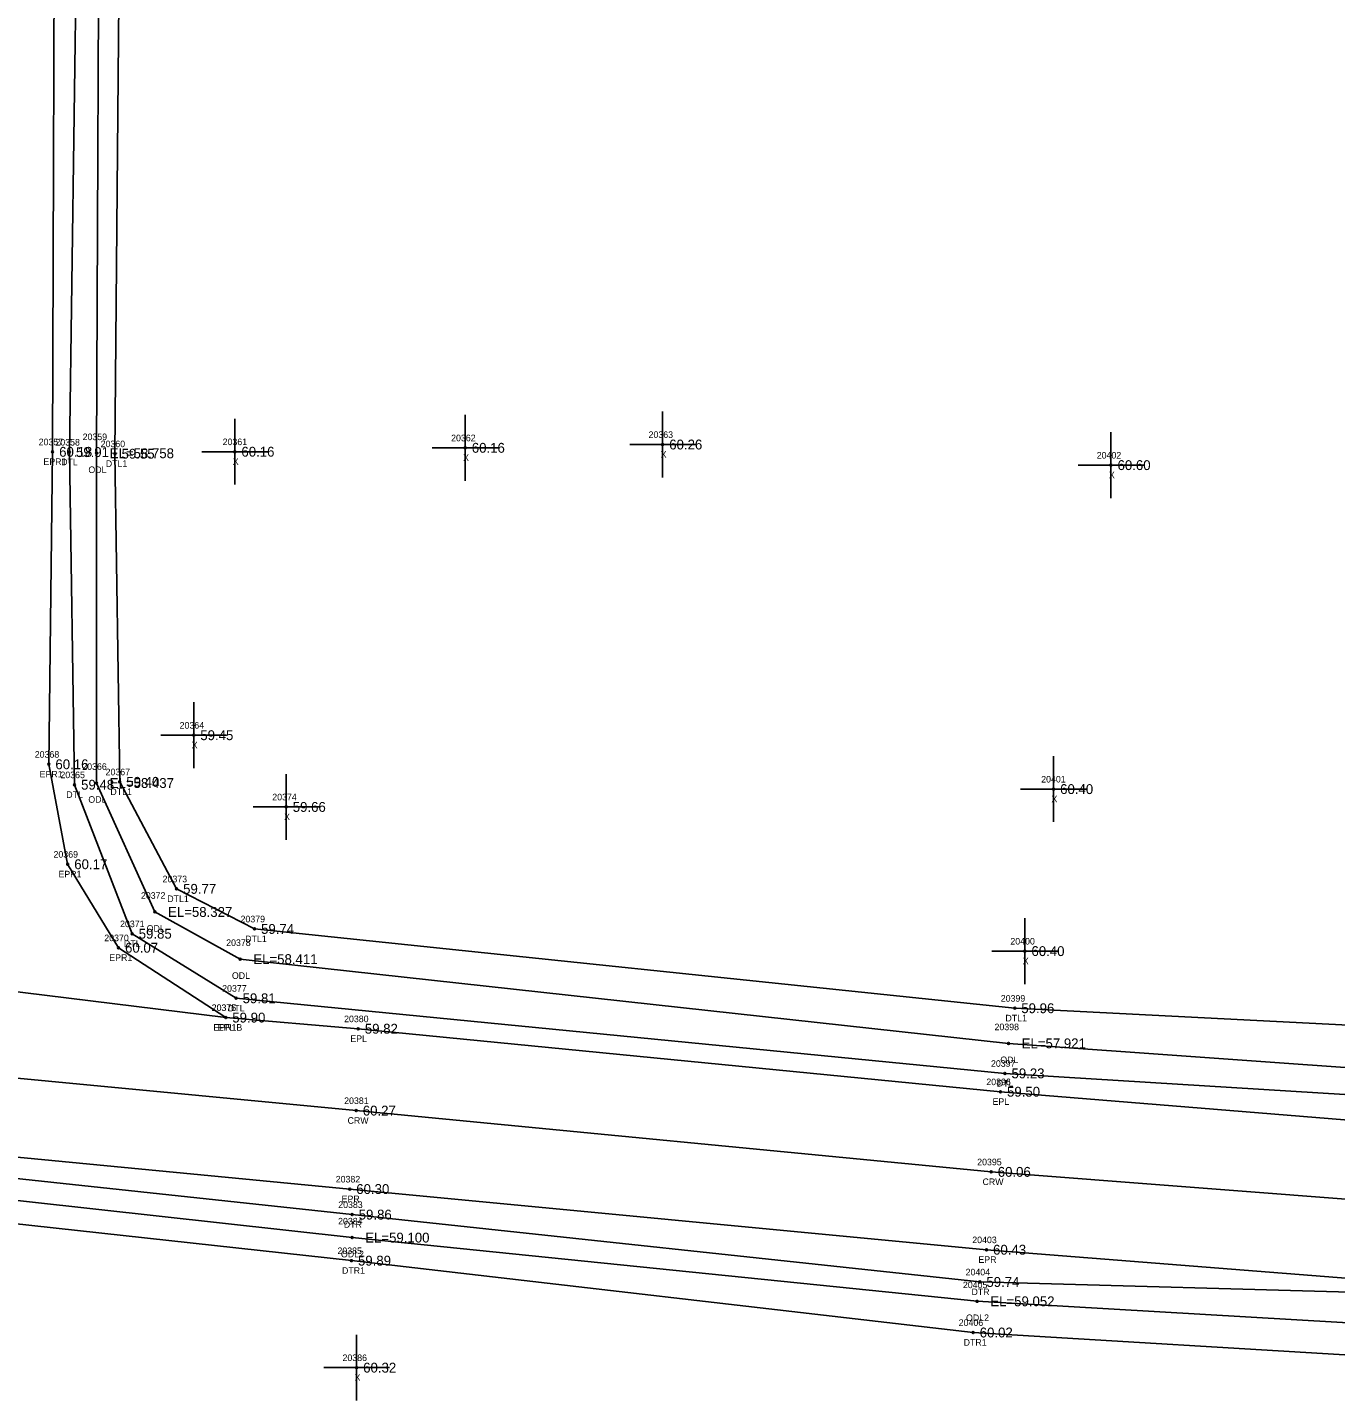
# Model space of a CAD drawing. Extents: x 2420351 to 2422725, y 845330 to 846558.
# Drawn here: x 2420968.2 to 2421166.9, y 845650.1 to 845858.7 of the extents above; entities that cross this region are included whole.
import ezdxf

# ---------------------------------------------------------------- set-up
doc = ezdxf.new("R2010")
doc.units = 0
for name, color, linetype in [('RD_DTM_BkLn1', 7, 'Continuous'), ('RD_EX_H2O', 7, 'Continuous'), ('RD_EX_H2O_txCode', 7, 'Continuous'), ('RD_EX_Misc', 7, 'Continuous'), ('RD_EX_Misc_txCode', 7, 'Continuous'), ('RD_EX_Road', 7, 'Continuous'), ('RD_EX_Road_txCode', 7, 'Continuous'), ('RD_EX_TX_H2O_ELEV', 7, 'Continuous'), ('RD_EX_TX_Misc_ELEV', 7, 'Continuous'), ('RD_EX_TX_Road_ELEV', 7, 'Continuous'), ('RD_HC_Survey_ELEV', 7, 'Continuous'), ('RD_HC_Survey_txCode', 7, 'Continuous'), ('RD_SMD_Locator', 7, 'Continuous')]:
    doc.layers.add(name, color=color, linetype=linetype)

msp = doc.modelspace()

# ---------------------------------------------------------------- linework, layer by layer
at = {"layer": 'RD_DTM_BkLn1'}
msp.add_lwpolyline([(2420378.71, 845690.53), (2420439.5, 845704.09), (2420489.95, 845712.49), (2420551.89, 845719.42), (2420551.95, 845719.57), (2420607.12, 845722.67), (2420682.92, 845723.04), (2420749.65, 845719.68), (2420796.31, 845715.7), (2420900.74, 845705.33), (2421018.16, 845694.11), (2421114.61, 845684.8), (2421175.74, 845680.1), (2421234.97, 845678.35), (2421292.42, 845679.46), (2421350.56, 845683.65), (2421414.53, 845692.12), (2421472.54, 845703.63), (2421533.08, 845718.31), (2421555.4, 845725.02), (2421609.81, 845741.71), (2421666.58, 845762.88), (2421744.67, 845798.22)], dxfattribs=at)
at = {"layer": 'RD_EX_H2O'}
for points in [[(2420975.55, 846190.58), (2420976.37, 846105.11), (2420974.31, 845997.82), (2420976.03, 845896.74), (2420974.59, 845794.18), (2420975.37, 845743.63), (2420984.12, 845720.99), (2420999.91, 845711.18), (2421116.7, 845699.77), (2421177.35, 845696.01), (2421236.57, 845694.11), (2421292.07, 845694.75), (2421349.67, 845700.43), (2421411.57, 845706.56), (2421470.63, 845718.76), (2421529.96, 845732.93), (2421551.14, 845737.51), (2421602.97, 845753.33), (2421656.85, 845776.48), (2421724.45, 845805.15), (2421739.21, 845812.56)], [(2420980.17, 846190.47), (2420980.93, 846104.85), (2420980.02, 845997.99), (2420979.17, 845896.92), (2420978.72, 845794), (2420978.72, 845743.89), (2420987.58, 845724.3), (2421000.53, 845717.13), (2421117.24, 845704.33), (2421178.3, 845699.94), (2421237.1, 845697.97), (2421292.37, 845698.66), (2421349.43, 845702.84), (2421410.88, 845710.25), (2421469.94, 845721.7), (2421529.19, 845736.54), (2421550.26, 845742.27), (2421602, 845757.38), (2421655.89, 845778.44), (2421721.41, 845810.89), (2421742.22, 845823.45)], [(2420984.17, 846190.38), (2420983.45, 846105.14), (2420982.87, 845998.03), (2420982.41, 845897.21), (2420981.52, 845793.93), (2420982.23, 845744.07), (2420990.87, 845727.81), (2421002.71, 845721.72), (2421118.19, 845709.67), (2421178.8, 845706.59), (2421237.43, 845704.42), (2421292.29, 845705.88), (2421348.44, 845711.4), (2421408.11, 845718.43)], [(2420681.02, 845707.72), (2420749.24, 845704.74), (2420794.5, 845700.07), (2420899.98, 845690.96), (2421017.54, 845678.31), (2421112.89, 845668.07), (2421174.6, 845666.39), (2421234.64, 845664.08), (2421293.38, 845665.28), (2421351.67, 845667.88), (2421422.34, 845677.35), (2421426.88, 845673.47), (2421424.22, 845667.22)], [(2420680.88, 845704.69), (2420749.16, 845701.08), (2420794.33, 845696.81), (2420899.79, 845687.85), (2421017.53, 845674.81), (2421112.48, 845665.13), (2421174.04, 845661.58), (2421234.82, 845660.24), (2421294.09, 845659.38), (2421352.01, 845663.24), (2421417.66, 845672.42), (2421424.72, 845673.17)], [(2420681.1, 845702.44), (2420748.92, 845698.41), (2420794.23, 845693.69), (2420899.45, 845684.25), (2421017.43, 845671.31), (2421111.87, 845660.39), (2421174.2, 845656.63), (2421235.06, 845654.38), (2421294.9, 845653.67), (2421353.19, 845655.89), (2421424.22, 845667.22)]]:
    msp.add_lwpolyline(points, dxfattribs=at)
at = {"layer": 'RD_EX_Misc'}
for p, q in [((2421034.72, 845789.83), (2421034.72, 845799.83)), ((2421064.71, 845790.33), (2421064.71, 845800.33)), ((2420999.72, 845789.24), (2420999.72, 845799.24)), ((2421059.71, 845795.33), (2421069.71, 845795.33)), ((2421132.81, 845787.2), (2421132.81, 845797.2)), ((2420994.72, 845794.24), (2421004.72, 845794.24)), ((2421029.72, 845794.83), (2421039.72, 845794.83)), ((2421127.81, 845792.2), (2421137.81, 845792.2)), ((2420993.48, 845746.16), (2420993.48, 845756.16)), ((2420988.48, 845751.16), (2420998.48, 845751.16)), ((2421124.09, 845737.97), (2421124.09, 845747.97)), ((2421007.52, 845735.26), (2421007.52, 845745.26)), ((2421119.09, 845742.97), (2421129.09, 845742.97)), ((2421002.52, 845740.26), (2421012.52, 845740.26)), ((2421119.73, 845713.35), (2421119.73, 845723.35)), ((2421114.73, 845718.35), (2421124.73, 845718.35)), ((2421018.22, 845650.05), (2421018.22, 845660.05)), ((2421013.22, 845655.05), (2421023.22, 845655.05))]:
    msp.add_line(p, q, dxfattribs=at)
at = {"layer": 'RD_EX_Road'}
for points in [[(2420972.5, 846190.42), (2420972.73, 846105.63), (2420971.77, 845998.07), (2420972.4, 845896.57), (2420972.04, 845794.22), (2420971.47, 845746.74), (2420974.33, 845731.55), (2420982.05, 845718.86), (2420998.34, 845708.25)], [(2420388.28, 845680.39), (2420441.29, 845692.04), (2420492.62, 845700.7), (2420553.92, 845707.41), (2420607.69, 845710.85), (2420682.38, 845711.26), (2420749.44, 845707.27), (2420795.12, 845703.44), (2420900.28, 845693.42), (2421017.17, 845682.19), (2421113.9, 845672.97), (2421174.87, 845668.16), (2421234.59, 845666.13), (2421293, 845667.25), (2421351.24, 845671.5), (2421419.82, 845681.17), (2421463.19, 845688.63), (2421558.82, 845713.18), (2421614.57, 845730.45), (2421670.73, 845751.42), (2421735.61, 845780.5), (2421750.75, 845787.87), (2421744.67, 845798.22), (2421739.21, 845808.11)], [(2420376.35, 845701.93), (2420403.68, 845709.11), (2420436.45, 845715.41), (2420465.85, 845720.8), (2420487.58, 845724.76), (2420551.29, 845731.53), (2420607.05, 845734.89), (2420658.72, 845735.59), (2420682.86, 845735.47), (2420736.67, 845732.56), (2420795.4, 845727.65), (2420889.7, 845718.98), (2420911.08, 845716.87), (2420953.91, 845713.71), (2420998.34, 845708.25), (2421018.47, 845706.55), (2421116.02, 845696.98), (2421176.98, 845692), (2421235.85, 845690.14), (2421292.32, 845691.44), (2421350.22, 845695.49), (2421412.35, 845704.28)]]:
    msp.add_lwpolyline(points, dxfattribs=at)
at = {"layer": 'RD_SMD_Locator'}
for centre in [(2421064.71, 845795.33), (2420972.04, 845794.22), (2420974.59, 845794.18), (2420978.72, 845794), (2420981.52, 845793.93), (2420999.72, 845794.24), (2421034.72, 845794.83), (2421132.81, 845792.2), (2420993.48, 845751.16), (2420971.47, 845746.74), (2420975.37, 845743.63), (2420978.72, 845743.89), (2420982.23, 845744.07), (2421124.09, 845742.97), (2421007.52, 845740.26), (2420974.33, 845731.55), (2420990.87, 845727.81), (2420987.58, 845724.3), (2420984.12, 845720.99), (2421002.71, 845721.72), (2420982.05, 845718.86), (2421119.73, 845718.35), (2421000.53, 845717.13), (2420999.91, 845711.18), (2421118.19, 845709.67), (2420998.34, 845708.25), (2420998.34, 845708.25), (2421018.47, 845706.55), (2421117.24, 845704.33), (2421116.7, 845699.77), (2421116.02, 845696.98), (2421018.16, 845694.11), (2421114.61, 845684.8), (2421017.17, 845682.19), (2421017.54, 845678.31), (2421017.53, 845674.81), (2421113.9, 845672.97), (2421017.43, 845671.31), (2421112.89, 845668.07), (2421112.48, 845665.13), (2421111.87, 845660.39), (2421018.22, 845655.05)]:
    msp.add_circle(centre, 0.15, dxfattribs=at)

# ---------------------------------------------------------------- texts
at = {"layer": 'RD_EX_H2O_txCode'}
for s, p in [('20358', (2420972.47, 845795.18)), ('20359', (2420976.6, 845796)), ('20360', (2420979.34, 845794.93)), ('DTL', (2420973.34, 845792.18)), ('ODL', (2420977.48, 845791)), ('DTL1', (2420980.12, 845791.93)), ('20365', (2420973.23, 845744.63)), ('20366', (2420976.55, 845745.89)), ('20367', (2420980.09, 845745.07)), ('DTL1', (2420980.82, 845742.07)), ('DTL', (2420974.12, 845741.63)), ('ODL', (2420977.47, 845740.89)), ('20373', (2420988.75, 845728.81)), ('20372', (2420985.46, 845726.3)), ('DTL1', (2420989.46, 845725.81)), ('20371', (2420982.29, 845721.99)), ('ODL', (2420986.33, 845721.3)), ('20379', (2421000.59, 845722.72)), ('20378', (2420998.41, 845719.13)), ('DTL1', (2421001.3, 845719.72)), ('DTL', (2420982.88, 845718.99)), ('ODL', (2420999.28, 845714.13)), ('20377', (2420997.8, 845712.18)), ('20399', (2421116.07, 845710.67)), ('DTL', (2420998.67, 845709.18)), ('DTL1', (2421116.78, 845707.67)), ('20398', (2421115.12, 845706.33)), ('20397', (2421114.58, 845700.77)), ('ODL', (2421116, 845701.33)), ('DTL', (2421115.46, 845697.77)), ('20383', (2421015.43, 845679.31)), ('20384', (2421015.41, 845676.81)), ('DTR', (2421016.28, 845676.31)), ('20385', (2421015.31, 845672.31)), ('ODL2', (2421015.84, 845671.81)), ('DTR1', (2421016, 845669.31)), ('20404', (2421110.73, 845669.07)), ('20405', (2421110.32, 845667.13)), ('DTR', (2421111.62, 845666.07)), ('20406', (2421109.68, 845661.39)), ('ODL2', (2421110.79, 845662.13)), ('DTR1', (2421110.43, 845658.39))]:
    msp.add_text(s, height=1, dxfattribs=at).set_placement(p)
at = {"layer": 'RD_EX_Misc_txCode'}
for s, p in [('20363', (2421062.57, 845796.33)), ('20361', (2420997.87, 845795.24)), ('20362', (2421032.58, 845795.83)), ('X', (2420999.41, 845792.24)), ('X', (2421034.4, 845792.83)), ('X', (2421064.4, 845793.33)), ('20402', (2421130.65, 845793.2)), ('X', (2421132.5, 845790.2)), ('20364', (2420991.34, 845752.16)), ('X', (2420993.17, 845749.16)), ('20401', (2421122.21, 845743.97)), ('20374', (2421005.41, 845741.26)), ('X', (2421123.77, 845740.97)), ('X', (2421007.21, 845738.26)), ('20400', (2421117.53, 845719.35)), ('X', (2421119.41, 845716.35)), ('20386', (2421016.08, 845656.05)), ('X', (2421017.91, 845653.05))]:
    msp.add_text(s, height=1, dxfattribs=at).set_placement(p)
at = {"layer": 'RD_EX_Road_txCode'}
for s, p in [('20357', (2420969.93, 845795.22)), ('EPR1', (2420970.65, 845792.22)), ('20368', (2420969.33, 845747.74)), ('EPR1', (2420970.07, 845744.74)), ('20369', (2420972.18, 845732.55)), ('EPR1', (2420972.93, 845729.55)), ('20370', (2420979.89, 845719.86)), ('EPR1', (2420980.65, 845716.86)), ('20376', (2420996.2, 845709.25)), ('20375', (2420996.22, 845709.25)), ('20380', (2421016.32, 845707.55)), ('EPR1B', (2420996.47, 845706.25)), ('EPL', (2420997.13, 845706.25)), ('EPL', (2421017.27, 845704.55)), ('20396', (2421113.88, 845697.98)), ('EPL', (2421114.82, 845694.98)), ('20382', (2421015.05, 845683.19)), ('EPR', (2421015.94, 845680.19)), ('20403', (2421111.74, 845673.97)), ('EPR', (2421112.67, 845670.97))]:
    msp.add_text(s, height=1, dxfattribs=at).set_placement(p)
at = {"layer": 'RD_EX_TX_H2O_ELEV'}
for s, p in [('59.91', (2420975.59, 845793.43)), ('EL=58.758', (2420980.72, 845793.25)), ('59.55', (2420982.52, 845793.18)), ('59.48', (2420976.37, 845742.88)), ('EL=58.437', (2420980.72, 845743.14)), ('59.40', (2420983.23, 845743.32)), ('59.77', (2420991.87, 845727.06)), ('EL=58.327', (2420989.58, 845723.55)), ('59.74', (2421003.71, 845720.97)), ('59.85', (2420985.12, 845720.24)), ('EL=58.411', (2421002.53, 845716.38)), ('59.81', (2421000.91, 845710.43)), ('59.96', (2421119.19, 845708.92)), ('EL=57.921', (2421119.24, 845703.58)), ('59.23', (2421117.7, 845699.02)), ('59.86', (2421018.54, 845677.56)), ('EL=59.100', (2421019.53, 845674.06)), ('59.89', (2421018.43, 845670.56)), ('59.74', (2421113.89, 845667.32)), ('EL=59.052', (2421114.48, 845664.38)), ('60.02', (2421112.87, 845659.64))]:
    msp.add_text(s, height=1.5, dxfattribs=at).set_placement(p)
at = {"layer": 'RD_EX_TX_Misc_ELEV'}
for s, p in [('60.16', (2421035.72, 845794.08)), ('60.26', (2421065.71, 845794.58)), ('60.16', (2421000.72, 845793.49)), ('60.60', (2421133.81, 845791.45)), ('59.45', (2420994.48, 845750.41)), ('60.40', (2421125.09, 845742.22)), ('59.66', (2421008.52, 845739.51)), ('60.40', (2421120.73, 845717.6)), ('60.32', (2421019.22, 845654.3))]:
    msp.add_text(s, height=1.5, dxfattribs=at).set_placement(p)
at = {"layer": 'RD_EX_TX_Road_ELEV'}
for s, p in [('60.18', (2420973.04, 845793.47)), ('60.16', (2420972.47, 845745.99)), ('60.17', (2420975.33, 845730.8)), ('60.07', (2420983.05, 845718.11)), ('59.90', (2420999.34, 845707.5)), ('59.90', (2420999.34, 845707.5)), ('59.82', (2421019.47, 845705.8)), ('59.50', (2421117.02, 845696.23)), ('60.30', (2421018.17, 845681.44)), ('60.43', (2421114.9, 845672.22))]:
    msp.add_text(s, height=1.5, dxfattribs=at).set_placement(p)
at = {"layer": 'RD_HC_Survey_ELEV'}
for s, p in [('60.27', (2421019.16, 845693.36)), ('60.06', (2421115.61, 845684.05))]:
    msp.add_text(s, height=1.5, dxfattribs=at).set_placement(p)
at = {"layer": 'RD_HC_Survey_txCode'}
for s, p in [('20381', (2421016.33, 845695.11)), ('CRW', (2421016.85, 845692.11)), ('20395', (2421112.49, 845685.8)), ('CRW', (2421113.3, 845682.8))]:
    msp.add_text(s, height=1, dxfattribs=at).set_placement(p)

doc.saveas('drawing.dxf')
